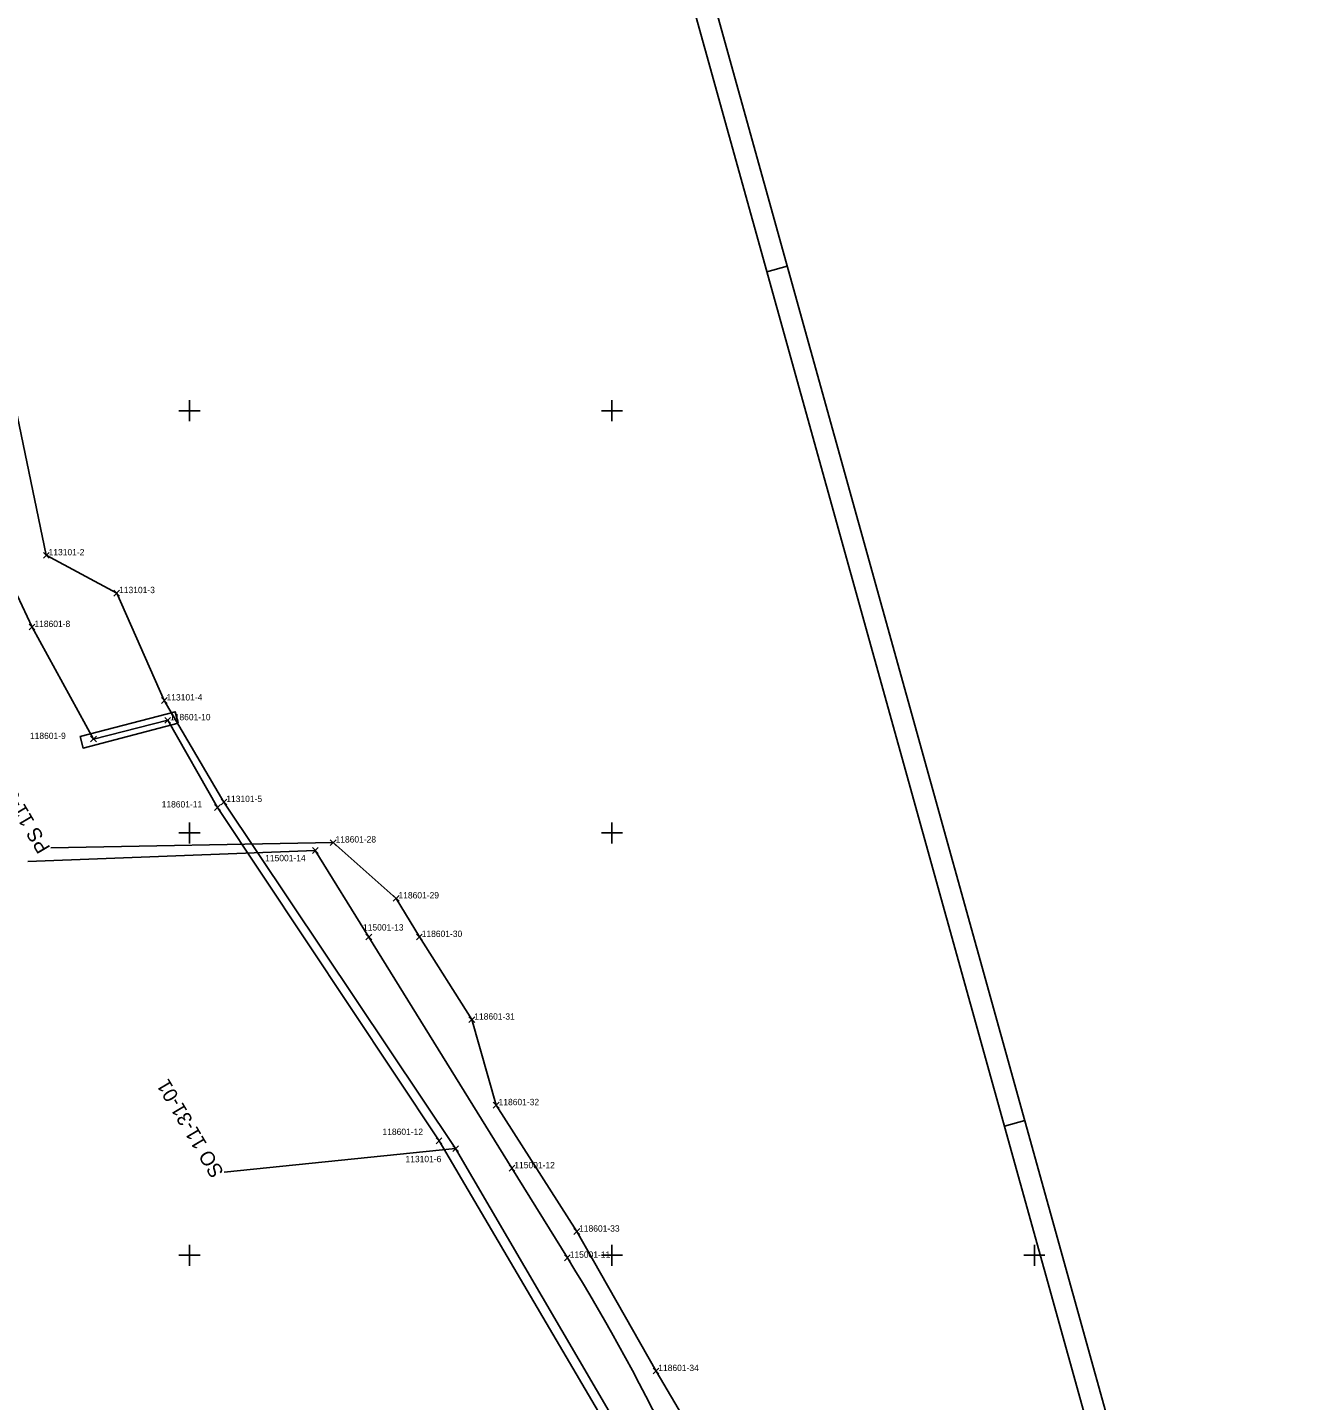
# Model space of a CAD drawing. Extents: x -821029 to -820632, y -1070881 to -1069931.
# Drawn here: x -820919.2 to -820766.8, y -1070267.2 to -1070104.6 of the extents above; entities that cross this region are included whole.
import ezdxf

# ---------------------------------------------------------------- set-up
doc = ezdxf.new("R2010")
doc.units = 0
for name, color, linetype in [('_PS_SO_číslo', 7, 'Continuous'), ('PS-11-02-31', 7, 'Continuous'), ('PS-11-02-41', 7, 'Continuous'), ('PS-11-02-92', 7, 'Continuous'), ('Ram', 7, 'Continuous'), ('Sit', 7, 'Continuous'), ('SO-11-31-01', 7, 'Continuous'), ('SO-11-50-01', 7, 'Continuous'), ('SO-11-86-01', 7, 'Continuous'), ('VB_SO-11-31-01', 7, 'Continuous'), ('VB_SO-11-50-01', 7, 'Continuous'), ('VB_SO-11-86-01', 7, 'Continuous')]:
    doc.layers.add(name, color=color, linetype=linetype)

msp = doc.modelspace()

# ---------------------------------------------------------------- linework, layer by layer
at = {"layer": '_PS_SO_číslo'}
for p, q in [((-820882.99, -1070201.13), (-820916.42, -1070201.76)), ((-820885.11, -1070202.07), (-820919.13, -1070203.37)), ((-820868.5, -1070237.37), (-820895.88, -1070240.18))]:
    msp.add_line(p, q, dxfattribs=at)
at = {"layer": 'PS-11-02-31'}
msp.add_lwpolyline([(-820959.28, -1070122.22), (-820934.84, -1070144.09), (-820933, -1070146.6), (-820925.15, -1070161.74), (-820918.63, -1070175.61), (-820911.37, -1070188.87), (-820902.58, -1070186.65), (-820896.69, -1070196.98), (-820870.46, -1070236.45), (-820846.57, -1070277.08), (-820842.6, -1070282.11), (-820813.47, -1070365.17), (-820809.8, -1070374.33), (-820792.8, -1070426.72), (-820792.34, -1070428.47), (-820790.08, -1070430.86), (-820788.92, -1070435.58), (-820780.39, -1070470.86), (-820770.55, -1070511.61), (-820767.89, -1070524.68), (-820765.3, -1070562.4), (-820759.61, -1070562.18)], dxfattribs=at)
at = {"layer": 'PS-11-02-41'}
msp.add_lwpolyline([(-820882.99, -1070201.13), (-820875.54, -1070207.75), (-820872.79, -1070212.31), (-820866.57, -1070222.1), (-820863.69, -1070232.23), (-820854.15, -1070247.2), (-820844.78, -1070263.71), (-820834.74, -1070280.72), (-820830.77, -1070287.4), (-820826.6, -1070295.78), (-820822.74, -1070307.42), (-820822.4, -1070310.54), (-820820.82, -1070316.36), (-820815.08, -1070335.82), (-820806.04, -1070362.21), (-820801.05, -1070374.78), (-820795.98, -1070387.28), (-820794.84, -1070388), (-820792.15, -1070393.19), (-820783.48, -1070412.23), (-820783.6, -1070416.46), (-820783.6, -1070418.02), (-820782.43, -1070424.35)], dxfattribs=at)
at = {"layer": 'PS-11-02-92'}
msp.add_lwpolyline([(-820882.99, -1070201.13), (-820875.54, -1070207.75), (-820872.79, -1070212.31), (-820866.57, -1070222.1), (-820863.69, -1070232.23), (-820854.15, -1070247.2), (-820844.78, -1070263.71), (-820834.74, -1070280.72), (-820830.77, -1070287.4), (-820826.6, -1070295.78), (-820822.74, -1070307.42), (-820822.4, -1070310.54), (-820820.82, -1070316.36), (-820815.08, -1070335.82), (-820806.04, -1070362.21), (-820801.05, -1070374.78), (-820795.98, -1070387.28), (-820794.84, -1070388), (-820792.15, -1070393.19), (-820783.48, -1070412.23), (-820783.6, -1070416.46), (-820783.6, -1070418.02), (-820782.43, -1070424.35)], dxfattribs=at)
at = {"layer": 'Ram'}
for p, q in [((-820829.24, -1070132.89), (-820831.65, -1070133.56)), ((-820801.13, -1070234.05), (-820803.54, -1070234.72))]:
    msp.add_line(p, q, dxfattribs=at)
for points in [[(-820857.35, -1070031.72), (-820632.46, -1070841.06), (-820775.54, -1070880.81), (-821000.43, -1070071.48)], [(-820859.09, -1070034.8), (-820635.54, -1070839.32), (-820773.8, -1070877.73), (-820997.35, -1070073.22)]]:
    msp.add_lwpolyline(points, dxfattribs=at)
at = {"layer": 'Sit'}
for p, q in [((-820900, -1070148.75), (-820900, -1070150)), ((-820850, -1070148.75), (-820850, -1070150)), ((-820901.25, -1070150), (-820900, -1070150)), ((-820898.75, -1070150), (-820900, -1070150)), ((-820900, -1070151.25), (-820900, -1070150)), ((-820851.25, -1070150), (-820850, -1070150)), ((-820848.75, -1070150), (-820850, -1070150)), ((-820850, -1070151.25), (-820850, -1070150)), ((-820901.25, -1070200), (-820900, -1070200)), ((-820900, -1070198.75), (-820900, -1070200)), ((-820898.75, -1070200), (-820900, -1070200)), ((-820900, -1070201.25), (-820900, -1070200)), ((-820851.25, -1070200), (-820850, -1070200)), ((-820850, -1070198.75), (-820850, -1070200)), ((-820848.75, -1070200), (-820850, -1070200)), ((-820850, -1070201.25), (-820850, -1070200)), ((-820900, -1070248.75), (-820900, -1070250)), ((-820850, -1070248.75), (-820850, -1070250)), ((-820800, -1070248.75), (-820800, -1070250)), ((-820800, -1070248.75), (-820800, -1070250)), ((-820901.25, -1070250), (-820900, -1070250)), ((-820898.75, -1070250), (-820900, -1070250)), ((-820900, -1070251.25), (-820900, -1070250)), ((-820851.25, -1070250), (-820850, -1070250)), ((-820848.75, -1070250), (-820850, -1070250)), ((-820850, -1070251.25), (-820850, -1070250)), ((-820801.25, -1070250), (-820800, -1070250)), ((-820801.25, -1070250), (-820800, -1070250)), ((-820798.75, -1070250), (-820800, -1070250)), ((-820800, -1070251.25), (-820800, -1070250)), ((-820800, -1070251.25), (-820800, -1070250)), ((-820798.75, -1070250), (-820800, -1070250))]:
    msp.add_line(p, q, dxfattribs=at)
at = {"layer": 'SO-11-31-01'}
msp.add_lwpolyline([(-820926.07, -1070123.29), (-820916.95, -1070167.12), (-820908.61, -1070171.6), (-820902.99, -1070184.31), (-820895.92, -1070196.33), (-820868.5, -1070237.37), (-820845.66, -1070276.46), (-820841.66, -1070281.51), (-820839.82, -1070285.2), (-820808.13, -1070374.18), (-820790.33, -1070426.97), (-820782.93, -1070433.41), (-820769.19, -1070488.5), (-820779.76, -1070491.37)], dxfattribs=at)
at = {"layer": 'SO-11-50-01'}
msp.add_lwpolyline([(-820885.11, -1070202.07), (-820878.77, -1070212.32), (-820861.83, -1070239.7), (-820855.27, -1070250.3)], dxfattribs=at)
msp.add_arc((-821067.95, -1070381.86), 250.08, 19.1742, 31.7407, dxfattribs=at)
at = {"layer": 'SO-11-86-01'}
for points in [[(-820955.09, -1070090.19), (-820959.28, -1070122.22), (-820934.84, -1070144.09), (-820933, -1070146.6), (-820925.15, -1070161.74), (-820918.63, -1070175.61), (-820911.37, -1070188.87), (-820902.58, -1070186.65), (-820896.69, -1070196.98), (-820870.46, -1070236.45), (-820846.57, -1070277.08)], [(-820882.99, -1070201.13), (-820875.54, -1070207.75), (-820872.79, -1070212.31), (-820866.57, -1070222.1), (-820863.69, -1070232.23), (-820854.15, -1070247.2), (-820844.78, -1070263.71), (-820834.74, -1070280.72)]]:
    msp.add_lwpolyline(points, dxfattribs=at)
msp.add_lwpolyline([(-820912.95, -1070188.59), (-820912.59, -1070189.95), (-820901.35, -1070187), (-820901.71, -1070185.64)], close=True, dxfattribs=at)
at = {"layer": 'VB_SO-11-31-01'}
for p, q in [((-820917.29, -1070167.46), (-820916.61, -1070166.78)), ((-820916.61, -1070167.46), (-820917.29, -1070166.78)), ((-820908.95, -1070171.94), (-820908.27, -1070171.26)), ((-820908.27, -1070171.94), (-820908.95, -1070171.26)), ((-820903.33, -1070184.65), (-820902.65, -1070183.97)), ((-820902.65, -1070184.65), (-820903.33, -1070183.97)), ((-820896.26, -1070196.67), (-820895.58, -1070195.99)), ((-820895.58, -1070196.67), (-820896.26, -1070195.99)), ((-820868.84, -1070237.71), (-820868.16, -1070237.03)), ((-820868.16, -1070237.71), (-820868.84, -1070237.03))]:
    msp.add_line(p, q, dxfattribs=at)
at = {"layer": 'VB_SO-11-50-01'}
for p, q in [((-820885.45, -1070202.42), (-820884.76, -1070201.73)), ((-820884.76, -1070202.42), (-820885.45, -1070201.73)), ((-820879.11, -1070212.66), (-820878.42, -1070211.97)), ((-820878.42, -1070212.66), (-820879.11, -1070211.97)), ((-820862.17, -1070240.04), (-820861.49, -1070239.35)), ((-820861.49, -1070240.04), (-820862.17, -1070239.35)), ((-820855.61, -1070250.64), (-820854.93, -1070249.95)), ((-820854.93, -1070250.64), (-820855.61, -1070249.95))]:
    msp.add_line(p, q, dxfattribs=at)
at = {"layer": 'VB_SO-11-86-01'}
for p, q in [((-820918.97, -1070175.95), (-820918.29, -1070175.27)), ((-820918.29, -1070175.95), (-820918.97, -1070175.27)), ((-820902.93, -1070186.99), (-820902.24, -1070186.31)), ((-820902.24, -1070186.99), (-820902.93, -1070186.31)), ((-820911.71, -1070189.22), (-820911.02, -1070188.53)), ((-820911.02, -1070189.22), (-820911.71, -1070188.53)), ((-820897.03, -1070197.32), (-820896.34, -1070196.63)), ((-820896.34, -1070197.32), (-820897.03, -1070196.63)), ((-820883.33, -1070201.47), (-820882.64, -1070200.79)), ((-820882.64, -1070201.47), (-820883.33, -1070200.79)), ((-820875.88, -1070208.09), (-820875.19, -1070207.41)), ((-820875.19, -1070208.09), (-820875.88, -1070207.41)), ((-820873.13, -1070212.66), (-820872.44, -1070211.97)), ((-820872.44, -1070212.66), (-820873.13, -1070211.97)), ((-820866.92, -1070222.45), (-820866.23, -1070221.76)), ((-820866.23, -1070222.45), (-820866.92, -1070221.76)), ((-820864.04, -1070232.57), (-820863.35, -1070231.88)), ((-820863.35, -1070232.57), (-820864.04, -1070231.88)), ((-820870.8, -1070236.8), (-820870.12, -1070236.11)), ((-820870.12, -1070236.8), (-820870.8, -1070236.11)), ((-820854.5, -1070247.54), (-820853.81, -1070246.85)), ((-820853.81, -1070247.54), (-820854.5, -1070246.85)), ((-820845.13, -1070264.05), (-820844.44, -1070263.36)), ((-820844.44, -1070264.05), (-820845.13, -1070263.36))]:
    msp.add_line(p, q, dxfattribs=at)

# ---------------------------------------------------------------- texts
at = {"layer": '_PS_SO_číslo'}
for s, p in [('PS 11-02-92', (-820916.42, -1070201.76)), ('SO 11-31-01', (-820895.88, -1070240.18))]:
    msp.add_text(s, height=1.7, rotation=120.6328, dxfattribs=at).set_placement(p)
at = {"layer": 'VB_SO-11-31-01'}
for s, p in [(' 113101-2', (-820916.95, -1070167.12)), (' 113101-3', (-820908.61, -1070171.6)), (' 113101-4', (-820902.99, -1070184.31)), (' 113101-5', (-820895.92, -1070196.33)), (' 113101-6', (-820874.71, -1070238.98))]:
    msp.add_text(s, height=0.75, dxfattribs=at).set_placement(p)
at = {"layer": 'VB_SO-11-50-01'}
for s, p in [(' 115001-14', (-820891.32, -1070203.34)), (' 115001-13', (-820879.74, -1070211.55)), (' 115001-12', (-820861.83, -1070239.7)), (' 115001-11', (-820855.27, -1070250.3))]:
    msp.add_text(s, height=0.75, dxfattribs=at).set_placement(p)
at = {"layer": 'VB_SO-11-86-01'}
for s, p in [(' 118601-8', (-820918.63, -1070175.61)), (' 118601-10', (-820902.58, -1070186.65)), (' 118601-9', (-820919.16, -1070188.87)), (' 118601-11', (-820903.57, -1070196.98)), (' 118601-28', (-820882.99, -1070201.13)), (' 118601-29', (-820875.54, -1070207.75)), (' 118601-30', (-820872.79, -1070212.31)), (' 118601-31', (-820866.57, -1070222.1)), (' 118601-32', (-820863.69, -1070232.23)), (' 118601-12', (-820877.43, -1070235.75)), (' 118601-33', (-820854.16, -1070247.2)), (' 118601-34', (-820844.79, -1070263.71))]:
    msp.add_text(s, height=0.75, dxfattribs=at).set_placement(p)

doc.saveas('drawing.dxf')
